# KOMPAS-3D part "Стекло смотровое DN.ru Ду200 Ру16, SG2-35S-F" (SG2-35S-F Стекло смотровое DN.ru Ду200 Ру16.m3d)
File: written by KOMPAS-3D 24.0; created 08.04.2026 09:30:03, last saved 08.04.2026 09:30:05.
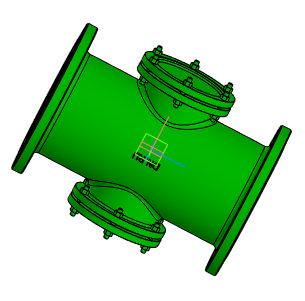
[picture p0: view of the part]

Document properties: Автор: Main; Полное имя файла: D:\DN.ru Аутсерс\Стекло смотровое DN.ru\SG2-35S-F Стекло смотровое DN.ru Ду200 Ру16\SG2-35S-F Стекло смотровое DN.ru Ду200 Ру16.m3d

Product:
- Body: Тело 1  | qty 1
    Масса: 65.830714
- Part/product: Стекло смотровое DN.ru Ду200 Ру16  | designation SG2-35S-F
    Масса: 55
    Раздел спецификации: Прочие изделия
    Примечание: D500-00102

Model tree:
1. Операция без истории:1

Expressions: SG2-35S-F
